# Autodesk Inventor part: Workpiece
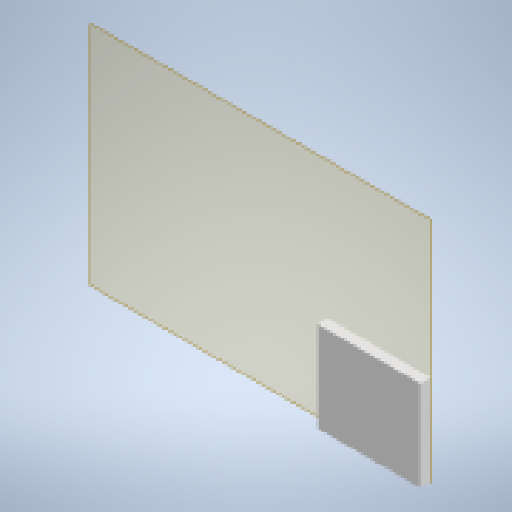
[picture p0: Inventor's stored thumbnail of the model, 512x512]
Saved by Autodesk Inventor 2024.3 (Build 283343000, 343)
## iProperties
Created: 2024-12
Part Number: Workpiece
Material: Generic
Document SubType Name: Modeling
Designer: ruhr
Density: 1 g/cm^3
Appearance: Default
Author: ruhr
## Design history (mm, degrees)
workplane "Work Plane1"
sketch "Sketch1"
  geometry: L1 (131.472, -87.961)-(51.472, -87.961); L2 (51.472, -87.961)-(51.472, -17.961); L3 (51.472, -17.961)-(131.472, -17.961); L4 (131.472, -17.961)-(131.472, -87.961); 1 further point
  constraints: 8 end point, 2 parallel, 1 horizontal, 1 perpendicular
  dimensions: "d0" = 80 distance of L2.end L3.end; "d1" = 70 distance of L1.end L2.end
extrude "Extrusion1" new body sketch "Sketch1" distance "d2" = 8; taper "d3" = 0 deg
body "Solid1"
